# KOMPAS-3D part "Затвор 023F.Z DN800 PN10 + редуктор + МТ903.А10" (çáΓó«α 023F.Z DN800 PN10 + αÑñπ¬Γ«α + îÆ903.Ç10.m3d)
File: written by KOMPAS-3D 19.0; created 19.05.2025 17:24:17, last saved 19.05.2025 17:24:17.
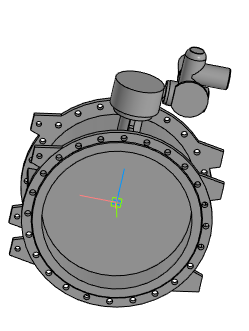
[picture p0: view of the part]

Document properties: Полное имя файла: Затвор 023F.Z DN800 PN10 + редуктор + МТ903.А10.a3d

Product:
- Part/product: Затвор 023F.Z DN800 PN10 + редуктор + МТ903.А10
    Масса: 824.981

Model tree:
1. Операция без истории:1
